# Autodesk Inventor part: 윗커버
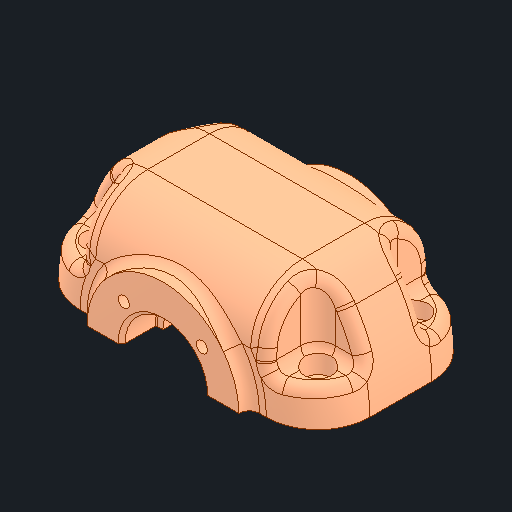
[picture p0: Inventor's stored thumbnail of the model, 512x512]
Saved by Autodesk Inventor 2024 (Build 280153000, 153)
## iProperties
Created: 2024-05
Part Number: 윗커버
Material: 알루미늄 6061
Document SubType Name: Modeling
Designer: kh_501
Density: 2.7 g/cm^3
Appearance: 기본값
Sending System: Autodesk Inventor 2025
Preprocessor: ST-DEVELOPER v20
Author: jhkim
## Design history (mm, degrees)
feature "솔리드1"
node "솔리드2"
